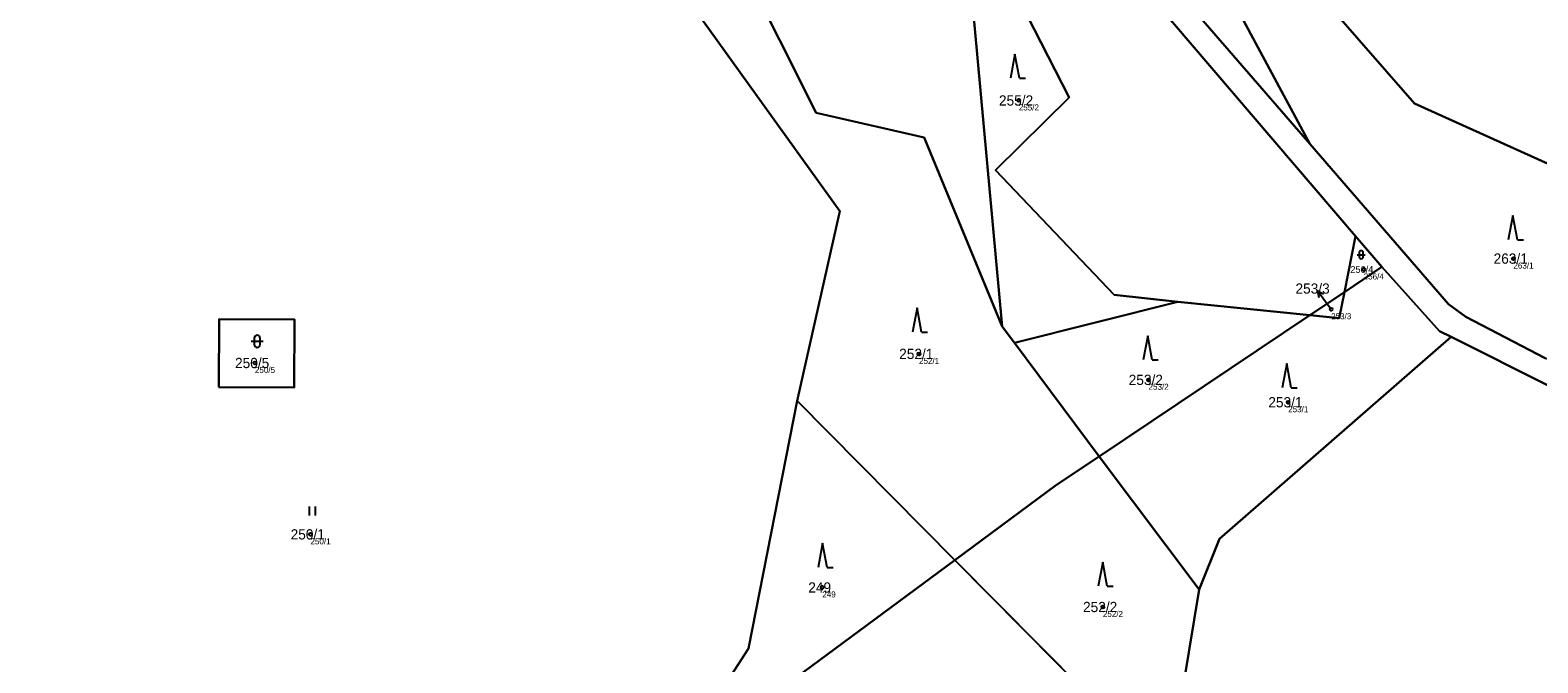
# Model space of a CAD drawing. Extents: x -554500 to -548272, y -1079733 to -1073730.
# Drawn here: x -551598.9 to -551348.5, y -1076793.5 to -1076688.4 of the extents above; entities that cross this region are included whole.
import ezdxf

# ---------------------------------------------------------------- set-up
doc = ezdxf.new("R2010")
doc.units = 0
for name, color, linetype in [('Definiční body', 7, 'Continuous'), ('Hranice parcel', 7, 'Continuous'), ('Parcelní čísla', 7, 'Continuous'), ('Polygon parcely', 7, 'Continuous'), ('Pop  PČ popisy', 7, 'Continuous'), ('Značky kultur', 7, 'Continuous')]:
    doc.layers.add(name, color=color, linetype=linetype)

msp = doc.modelspace()

# ---------------------------------------------------------------- linework, layer by layer
at = {"layer": 'Definiční body'}
for centre in [(-551434.74, -1076700.11994), (-551352.59, -1076726.36994), (-551377.46, -1076728.17994), (-551382.87, -1076734.77994), (-551451.31, -1076742.18994), (-551561.61, -1076743.69994), (-551413.19, -1076746.49994), (-551390, -1076750.21994), (-551552.38, -1076772.14994), (-551467.38, -1076780.96994), (-551420.78, -1076784.20994)]:
    msp.add_circle(centre, 0.25, dxfattribs=at)
at = {"layer": 'Hranice parcel'}
for p, q in [((-551380.66, -1076731.93), (-551378.8, -1076722.63)), ((-551378.8, -1076722.63), (-551374.42, -1076727.75)), ((-551374.42, -1076727.75), (-551380.66, -1076731.93)), ((-551386.4, -1076735.78), (-551380.66, -1076731.93)), ((-551408.31, -1076733.55), (-551435.46, -1076740.37)), ((-551386.4, -1076735.78), (-551408.31, -1076733.55)), ((-551386.4, -1076735.78), (-551421.37, -1076759.2)), ((-551435.46, -1076740.37), (-551437.51, -1076737.63)), ((-551421.37, -1076759.2), (-551435.46, -1076740.37)), ((-551445.36, -1076776.44), (-551471.57, -1076749.99)), ((-551404.81, -1076781.33), (-551421.37, -1076759.2)), ((-551409.89, -1076812.21), (-551445.36, -1076776.44)), ((-551409.89, -1076812.21), (-551404.81, -1076781.33))]:
    msp.add_line(p, q, dxfattribs=at)
for points in [[(-551449.14, -1076602.38), (-551444.34, -1076611.62), (-551441.72, -1076618.38), (-551440.22, -1076625.36), (-551426.41, -1076656.52), (-551411.77, -1076678.06), (-551386.41, -1076707.34)], [(-551378.8, -1076722.63), (-551416.06, -1076679.05), (-551430.2, -1076657.66), (-551442.76, -1076630.45), (-551447.26, -1076615.09)], [(-551437.51, -1076737.63), (-551450.45, -1076706.29), (-551468.39, -1076702.19), (-551480.58, -1076677.85), (-551505.64, -1076645.97), (-551507.97, -1076641.78), (-551512.47, -1076640.42), (-551523.97, -1076631.56)], [(-551424.79, -1076631.7), (-551426.88, -1076632.08), (-551386.41, -1076707.34)], [(-551301.37, -1076739.22), (-551321.69, -1076732.31), (-551330.25, -1076718.08), (-551369.04, -1076700.63), (-551405.37, -1076658.97), (-551424.79, -1076631.7)], [(-551408.31, -1076733.55), (-551418.88, -1076732.39), (-551438.6, -1076711.68), (-551426.39, -1076699.6), (-551440.38, -1076672.23), (-551450.71, -1076669.38)], [(-551437.51, -1076737.63), (-551442.57, -1076682.13), (-551450.71, -1076669.38)], [(-551471.57, -1076749.99), (-551464.47, -1076718.49), (-551488.37, -1076685.22)], [(-551097.2, -1076691.28), (-551114.06, -1076701.53), (-551156.46, -1076718.99), (-551178.01, -1076725.74), (-551210.07, -1076731.21), (-551297.96, -1076751.38), (-551325.92, -1076752.14), (-551346.51, -1076747.61), (-551362.93, -1076739.35)], [(-551386.41, -1076707.34), (-551363.38, -1076733.93), (-551360.49, -1076736.04), (-551347.32, -1076742.91), (-551324.66, -1076748.24), (-551298.76, -1076748.02)], [(-551362.93, -1076739.35), (-551364.85, -1076738.39), (-551374.42, -1076727.75)], [(-551380.66, -1076731.93), (-551381.53, -1076736.28), (-551386.4, -1076735.78)], [(-551567.58, -1076747.73), (-551567.53, -1076736.43), (-551555.03, -1076736.49), (-551555.08, -1076747.79), (-551567.58, -1076747.73)], [(-551404.81, -1076781.33), (-551401.4, -1076772.89), (-551362.93, -1076739.35)], [(-551471.57, -1076749.99), (-551479.61, -1076791.08), (-551491.75, -1076809.86), (-551494.17, -1076823.14), (-551495.31, -1076830.98)], [(-551445.36, -1076776.44), (-551428.46, -1076763.95), (-551421.37, -1076759.2)], [(-551445.36, -1076776.44), (-551479.79, -1076801.89), (-551495.31, -1076830.98)]]:
    msp.add_lwpolyline(points, dxfattribs=at)
at = {"layer": 'Polygon parcely'}
for points in [[(-551463.14, -1076648.98), (-551480.95, -1076642.45), (-551481.57, -1076644.48), (-551483.78, -1076651.75), (-551495.36, -1076648.23), (-551494.69, -1076646.03), (-551497.08, -1076645.3), (-551495.54, -1076640.23), (-551494.68, -1076637.41), (-551500.59, -1076635.24), (-551487.6, -1076600.53), (-551483.94, -1076590.73), (-551488.5, -1076588.85), (-551492.25, -1076598.3), (-551523.97, -1076631.56), (-551512.47, -1076640.42), (-551507.97, -1076641.78), (-551505.64, -1076645.97), (-551480.58, -1076677.85), (-551468.39, -1076702.19), (-551450.45, -1076706.29), (-551437.51, -1076737.63), (-551442.57, -1076682.13), (-551450.71, -1076669.38)], [(-551433.36, -1076619.68), (-551440.62, -1076607.37), (-551449.14, -1076602.38), (-551444.34, -1076611.62), (-551441.72, -1076618.38), (-551440.22, -1076625.36), (-551426.41, -1076656.52), (-551411.77, -1076678.06), (-551386.41, -1076707.34), (-551426.88, -1076632.08), (-551424.79, -1076631.7)], [(-551380.66, -1076731.93), (-551378.8, -1076722.63), (-551416.06, -1076679.05), (-551430.2, -1076657.66), (-551442.76, -1076630.45), (-551447.26, -1076615.09), (-551461.4, -1076645.26), (-551463.14, -1076648.98), (-551450.71, -1076669.38), (-551440.38, -1076672.23), (-551426.39, -1076699.6), (-551438.6, -1076711.68), (-551418.88, -1076732.39), (-551408.31, -1076733.55), (-551386.4, -1076735.78)], [(-551424.79, -1076631.7), (-551426.88, -1076632.08), (-551386.41, -1076707.34), (-551363.38, -1076733.93), (-551360.49, -1076736.04), (-551347.32, -1076742.91), (-551324.66, -1076748.24), (-551298.76, -1076748.02), (-551301.37, -1076739.22), (-551321.69, -1076732.31), (-551330.25, -1076718.08), (-551369.04, -1076700.63), (-551405.37, -1076658.97)], [(-551418.88, -1076732.39), (-551438.6, -1076711.68), (-551426.39, -1076699.6), (-551440.38, -1076672.23), (-551450.71, -1076669.38), (-551442.57, -1076682.13), (-551437.51, -1076737.63), (-551435.46, -1076740.37), (-551408.31, -1076733.55)], [(-551380.66, -1076731.93), (-551374.42, -1076727.75), (-551378.8, -1076722.63)], [(-551404.81, -1076781.33), (-551401.4, -1076772.89), (-551362.93, -1076739.35), (-551364.85, -1076738.39), (-551374.42, -1076727.75), (-551380.66, -1076731.93), (-551381.53, -1076736.28), (-551386.4, -1076735.78), (-551421.37, -1076759.2)], [(-551386.4, -1076735.78), (-551381.53, -1076736.28), (-551380.66, -1076731.93)], [(-551408.31, -1076733.55), (-551435.46, -1076740.37), (-551421.37, -1076759.2), (-551386.4, -1076735.78)], [(-551567.58, -1076747.73), (-551555.08, -1076747.79), (-551555.03, -1076736.49), (-551567.53, -1076736.43)], [(-551567.58, -1076747.73), (-551567.53, -1076736.43), (-551555.03, -1076736.49), (-551555.08, -1076747.79)], [(-551494.17, -1076823.14), (-551495.31, -1076830.98), (-551479.79, -1076801.89), (-551445.36, -1076776.44), (-551471.57, -1076749.99), (-551479.61, -1076791.08), (-551491.75, -1076809.86)], [(-551409.89, -1076812.21), (-551404.81, -1076781.33), (-551421.37, -1076759.2), (-551428.46, -1076763.95), (-551445.36, -1076776.44)], [(-551479.79, -1076801.89), (-551495.31, -1076830.98), (-551495.43, -1076831.77), (-551465.96, -1076849.32), (-551480.23, -1076875.5), (-551516.96, -1076928.64), (-551494.26, -1076941.85), (-551483.65, -1076954.04), (-551481, -1076957.09), (-551460.55, -1076919.48), (-551450.64, -1076860.41), (-551409.89, -1076812.21), (-551445.36, -1076776.44)]]:
    msp.add_lwpolyline(points, close=True, dxfattribs=at)
for points in [[(-551491.75, -1076809.86), (-551479.61, -1076791.08), (-551471.57, -1076749.99), (-551464.47, -1076718.49), (-551488.37, -1076685.22), (-551510.13, -1076669.53), (-551536.58, -1076658.37), (-551524.83, -1076645.4), (-551520.78, -1076640.92), (-551532.66, -1076630.28), (-551559.14, -1076615.99), (-551579.36, -1076646.57), (-551603.65, -1076638.88), (-551611.05, -1076662.17), (-551625.09, -1076706.38), (-551637.03, -1076742.94), (-551640.84, -1076765.63), (-551646.97, -1076786.61), (-551649.84, -1076794.7)], [(-551329.98, -1076701.18), (-551361.87, -1076671.8), (-551386.64, -1076661.17), (-551384.5, -1076644.08), (-551358.67, -1076629.2), (-551362.74, -1076620.4), (-551424.79, -1076631.7), (-551405.37, -1076658.97), (-551369.04, -1076700.63), (-551330.25, -1076718.08)], [(-551488.37, -1076685.22), (-551464.47, -1076718.49), (-551471.57, -1076749.99), (-551445.36, -1076776.44), (-551428.46, -1076763.95), (-551421.37, -1076759.2), (-551435.46, -1076740.37), (-551437.51, -1076737.63), (-551450.45, -1076706.29), (-551468.39, -1076702.19), (-551480.58, -1076677.85)], [(-551416.06, -1076679.05), (-551378.8, -1076722.63), (-551374.42, -1076727.75), (-551364.85, -1076738.39), (-551362.93, -1076739.35), (-551346.51, -1076747.61)], [(-551347.32, -1076742.91), (-551360.49, -1076736.04), (-551363.38, -1076733.93), (-551386.41, -1076707.34), (-551411.77, -1076678.06)], [(-551210.07, -1076731.21), (-551297.96, -1076751.38), (-551325.92, -1076752.14), (-551346.51, -1076747.61), (-551362.93, -1076739.35), (-551401.4, -1076772.89), (-551404.81, -1076781.33), (-551409.89, -1076812.21)]]:
    msp.add_lwpolyline(points, dxfattribs=at)
at = {"layer": 'Pop  PČ popisy'}
for p, q in [((-551383.35, -1076734.13), (-551385.114, -1076731.702)), ((-551385.114, -1076731.702), (-551384.12, -1076732.218)), ((-551385.114, -1076731.702), (-551384.93, -1076732.807)), ((-551382.87, -1076734.78), (-551383.35, -1076734.13))]:
    msp.add_line(p, q, dxfattribs=at)
at = {"layer": 'Značky kultur'}
for p, q in [((-551435.39, -1076692.43), (-551436.14, -1076696.43)), ((-551434.64, -1076696.43), (-551435.39, -1076692.43)), ((-551434.64, -1076696.43), (-551433.644, -1076696.43)), ((-551352.69, -1076719.24), (-551353.44, -1076723.24)), ((-551351.94, -1076723.24), (-551352.69, -1076719.24)), ((-551351.94, -1076723.24), (-551350.944, -1076723.24)), ((-551378.551, -1076725.731), (-551377.209, -1076725.731)), ((-551378.215, -1076725.395), (-551378.215, -1076726.066)), ((-551377.545, -1076726.066), (-551377.545, -1076725.395)), ((-551451.64, -1076734.56), (-551452.39, -1076738.56)), ((-551450.89, -1076738.56), (-551451.64, -1076734.56)), ((-551561.731, -1076739.601), (-551561.731, -1076740.602)), ((-551560.729, -1076740.602), (-551560.729, -1076739.601)), ((-551450.89, -1076738.56), (-551449.894, -1076738.56)), ((-551413.33, -1076739.17), (-551414.08, -1076743.17)), ((-551412.58, -1076743.17), (-551413.33, -1076739.17)), ((-551562.231, -1076740.101), (-551560.229, -1076740.101)), ((-551412.58, -1076743.17), (-551411.584, -1076743.17)), ((-551390.25, -1076743.81), (-551391, -1076747.81)), ((-551389.5, -1076747.81), (-551390.25, -1076743.81)), ((-551389.5, -1076747.81), (-551388.504, -1076747.81)), ((-551552.561, -1076769.02), (-551552.561, -1076767.52)), ((-551551.56, -1076769.02), (-551551.56, -1076767.52)), ((-551467.33, -1076773.63), (-551468.08, -1076777.63)), ((-551466.58, -1076777.63), (-551467.33, -1076773.63)), ((-551420.79, -1076776.76), (-551421.54, -1076780.76)), ((-551420.04, -1076780.76), (-551420.79, -1076776.76)), ((-551466.58, -1076777.63), (-551465.584, -1076777.63)), ((-551420.04, -1076780.76), (-551419.044, -1076780.76))]:
    msp.add_line(p, q, dxfattribs=at)
for centre, radius, start, end in [((-551377.88, -1076725.3956), 0.335, 0, 180), ((-551377.88, -1076726.0656), 0.335, 180, 359.9878861), ((-551561.23, -1076739.6009), 0.5, 0, 180), ((-551561.23, -1076740.6009), 0.5, 180, 359.9878861)]:
    msp.add_arc(centre, radius, start, end, dxfattribs=at)

# ---------------------------------------------------------------- texts
at = {"layer": 'Definiční body'}
for s, p in [('255/2', (-551434.74, -1076701.776)), ('263/1', (-551352.59, -1076728.026)), ('256/4', (-551377.46, -1076729.836)), ('253/3', (-551382.87, -1076736.436)), ('250/5', (-551561.61, -1076745.356)), ('252/1', (-551451.31, -1076743.846)), ('253/2', (-551413.19, -1076748.156)), ('253/1', (-551390, -1076751.876)), ('250/1', (-551552.38, -1076773.806)), ('249', (-551467.38, -1076782.626)), ('252/2', (-551420.78, -1076785.866))]:
    msp.add_text(s, height=0.999996, dxfattribs=at).set_placement(p)
at = {"layer": 'Parcelní čísla'}
for s, height, p in [('255/2', 1.699998, (-551438.038, -1076700.97)), ('263/1', 1.699998, (-551355.888, -1076727.22)), ('256/4', 1.14, (-551379.671, -1076728.75)), ('253/3', 1.699998, (-551388.787, -1076732.19)), ('252/1', 1.699998, (-551454.608, -1076743.04)), ('250/5', 1.699998, (-551564.908, -1076744.55)), ('253/2', 1.699998, (-551416.488, -1076747.35)), ('253/1', 1.699998, (-551393.298, -1076751.07)), ('250/1', 1.699998, (-551555.678, -1076773)), ('249', 1.699998, (-551469.705, -1076781.82)), ('252/2', 1.699998, (-551424.078, -1076785.06))]:
    msp.add_text(s, height=height, dxfattribs=at).set_placement(p)

doc.saveas('drawing.dxf')
